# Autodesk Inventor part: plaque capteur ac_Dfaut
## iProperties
Created: 2007-07
Part Number: plaque capteur ac_Dfaut
Document SubType Name: Modeling
Designer: EF
Density: 1 g/cm^3
Author: EF
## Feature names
1. Base1
